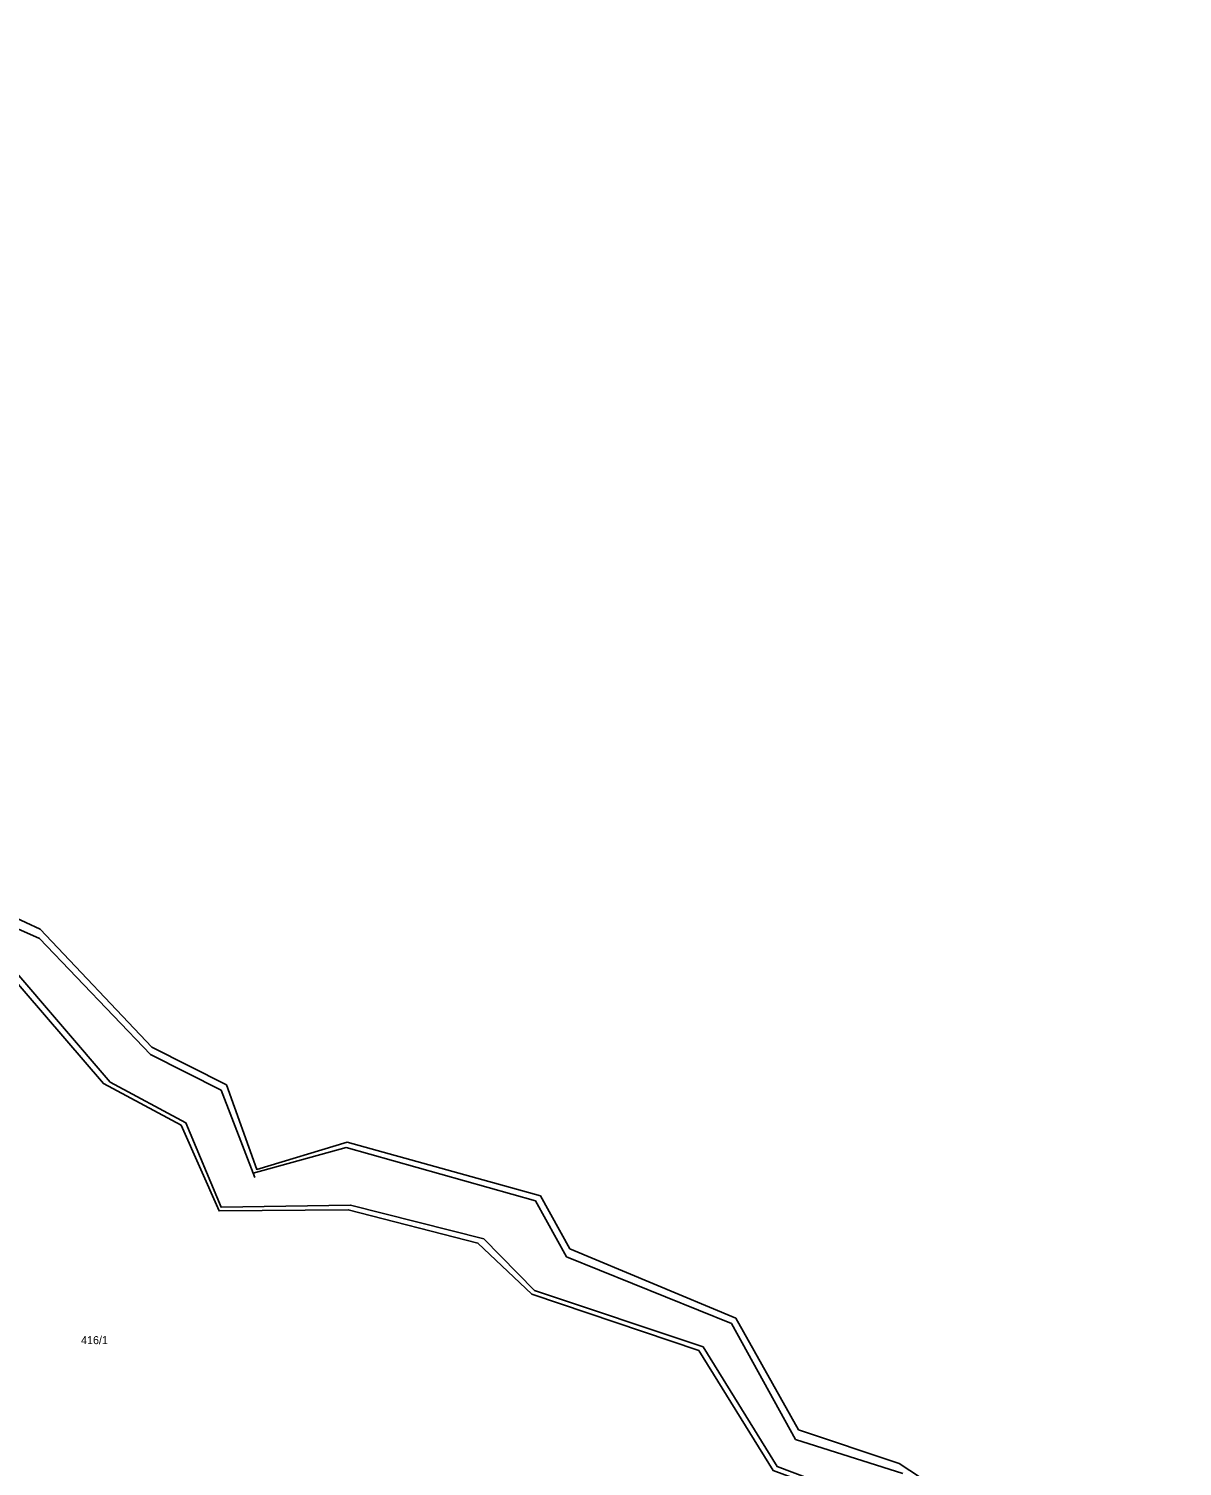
# Model space of a CAD drawing. Extents: x -887272 to -877616, y -1026687 to -1019819.
# Drawn here: x -879878.8 to -879633.8, y -1022445.1 to -1022139.8 of the extents above; entities that cross this region are included whole.
import ezdxf

# ---------------------------------------------------------------- set-up
doc = ezdxf.new("R2010")
doc.units = 0
for name, color, linetype in [('Hranice parcel', 7, 'Continuous'), ('Parcelní čísla', 7, 'Continuous'), ('Vnitřní kresba', 7, 'Continuous')]:
    doc.layers.add(name, color=color, linetype=linetype)

msp = doc.modelspace()

# ---------------------------------------------------------------- linework, layer by layer
at = {"layer": 'Hranice parcel'}
for p, q in [((-879836.8, -1022364.1), (-879852.62, -1022356.1)), ((-879763.86, -1022398.98), (-879770.1, -1022387.72)), ((-879728.59, -1022413.68), (-879763.86, -1022398.98)), ((-879670.97, -1022459.53), (-879693.89, -1022444.57))]:
    msp.add_line(p, q, dxfattribs=at)
for points in [[(-879852.62, -1022356.1), (-879876.34, -1022331.08), (-879900.8, -1022319.74), (-879917.41, -1022273.06), (-879904.07, -1022228.12), (-879891.86, -1022215.5), (-879913.95, -1022179.12), (-879927.16, -1022162.97), (-879953.53, -1022160.38), (-879979.51, -1022142.78), (-880011, -1022145.56), (-880011.84, -1022139.78)], [(-879633.8, -1022480.63), (-879660.6, -1022471.88), (-879677.81, -1022467.72), (-879699.12, -1022454.05), (-879720.69, -1022446.04), (-879736.48, -1022420.52), (-879771.92, -1022408.58), (-879783.4, -1022397.72), (-879810.92, -1022390.65), (-879838.37, -1022390.91), (-879846.45, -1022372.72), (-879862.92, -1022363.84), (-879883.64, -1022339.68), (-879913.23, -1022324.87), (-879930.34, -1022275.22), (-879914.25, -1022226.31)], [(-879770.1, -1022387.72), (-879811.18, -1022376.32), (-879830.38, -1022382.07), (-879836.8, -1022364.1)], [(-879693.89, -1022444.57), (-879715.3, -1022437.37), (-879728.59, -1022413.68)]]:
    msp.add_lwpolyline(points, dxfattribs=at)
at = {"layer": 'Vnitřní kresba'}
for p, q in [((-879901.77, -1022321.82), (-879876.48, -1022333)), ((-879876.48, -1022333), (-879852.93, -1022357.64)), ((-879852.93, -1022357.64), (-879837.91, -1022365.23)), ((-879837.91, -1022365.23), (-879830.78, -1022383.83)), ((-879771.18, -1022388.74), (-879764.55, -1022400.69)), ((-879764.55, -1022400.69), (-879729.54, -1022414.79)), ((-879729.54, -1022414.79), (-879715.91, -1022439.43)), ((-879715.91, -1022439.43), (-879693.14, -1022446.71))]:
    msp.add_line(p, q, dxfattribs=at)
for points in [[(-879912.42, -1022323.74), (-879882.14, -1022339.39), (-879861.47, -1022363.57), (-879845.41, -1022372.16), (-879837.93, -1022390.13), (-879810.43, -1022389.65), (-879782.15, -1022396.86), (-879771.34, -1022407.84), (-879735.56, -1022419.77), (-879719.82, -1022445.22), (-879697.88, -1022453.49), (-879677.21, -1022466.85), (-879660.2, -1022471.15), (-879634.44, -1022479.57)], [(-879831.15, -1022382.88), (-879811.34, -1022377.43), (-879771.18, -1022388.74)]]:
    msp.add_lwpolyline(points, dxfattribs=at)

# ---------------------------------------------------------------- texts
at = {"layer": 'Parcelní čísla'}
msp.add_text('416/1', height=1.7, dxfattribs=at).set_placement((-879867.67, -1022419.2))

doc.saveas('drawing.dxf')
